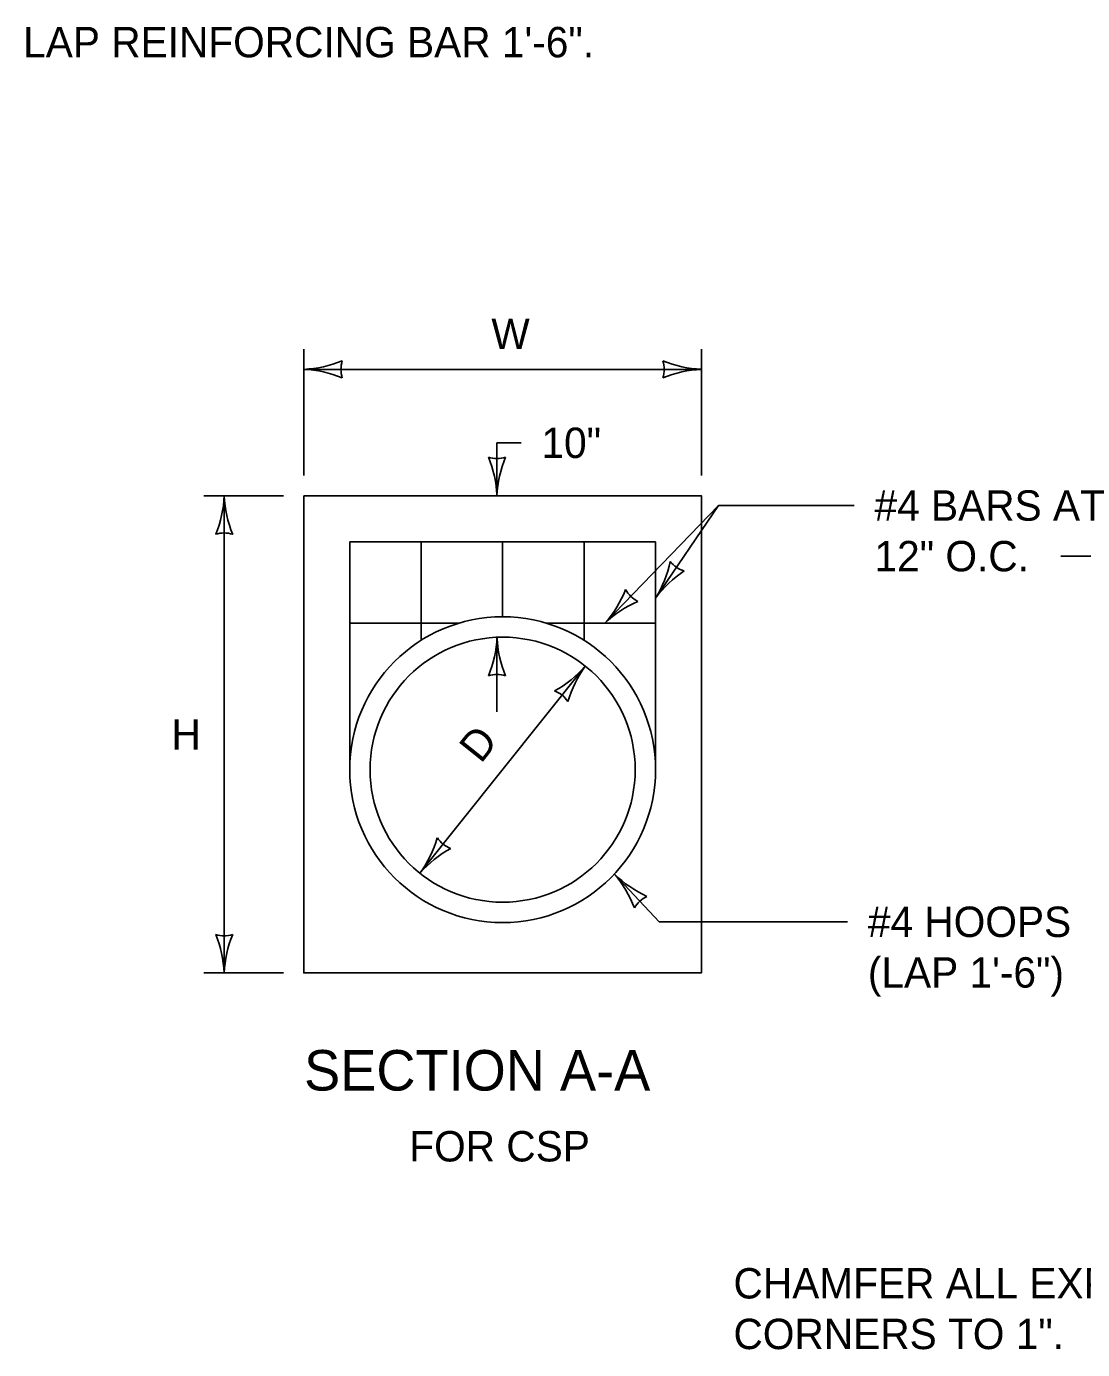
# Model space of a CAD drawing. Extents: x 49991.4 to 50043, y 49987.6 to 50011.4.
# Drawn here: x 50003.119 to 50005.204, y 49993.582 to 49996.195 of the extents above; entities that cross this region are included whole.
import ezdxf

# ---------------------------------------------------------------- set-up
doc = ezdxf.new("R2010")
doc.units = 0
for name, color, linetype in [('Level 1', 7, 'Continuous'), ('Level 2', 7, 'Continuous'), ('Level 3', 7, 'Continuous')]:
    doc.layers.add(name, color=color, linetype=linetype)

msp = doc.modelspace()

# ---------------------------------------------------------------- linework, layer by layer
at = {"layer": 'Level 1'}
for p, q in [((50003.7573, 49995.1771), (50004.3611, 49995.1771)), ((50003.7573, 49994.727), (50003.7573, 49995.1771)), ((50003.8984, 49995.1771), (50003.8984, 49994.9825)), ((50004.0592, 49995.0289), (50004.0592, 49995.1771)), ((50004.22, 49995.1771), (50004.22, 49994.9825)), ((50004.3611, 49995.1771), (50004.3611, 49994.727)), ((50003.7573, 49995.0164), (50003.9732, 49995.0164)), ((50004.1452, 49995.0164), (50004.3611, 49995.0164))]:
    msp.add_line(p, q, dxfattribs=at)
msp.add_lwpolyline([(50003.6666, 49995.2678), (50004.4518, 49995.2678), (50004.4518, 49994.3256), (50003.6666, 49994.3256)], close=True, dxfattribs=at)
for radius in [0.3019, 0.2617]:
    msp.add_circle((50004.0592, 49994.727), radius, dxfattribs=at)
at = {"layer": 'Level 3'}
for p, q in [((50003.6666, 49995.3078), (50003.6666, 49995.5576)), ((50004.4518, 49995.3078), (50004.4518, 49995.5576)), ((50003.6666, 49995.5176), (50004.4518, 49995.5176)), ((50004.0481, 49995.2678), (50004.0481, 49995.3725)), ((50004.0481, 49995.3725), (50004.0959, 49995.3725)), ((50003.6266, 49995.2678), (50003.4695, 49995.2678)), ((50003.5095, 49995.2678), (50003.5095, 49994.3256)), ((50004.4857, 49995.2487), (50004.2613, 49995.0164)), ((50004.4857, 49995.2487), (50004.3611, 49995.0659)), ((50004.7534, 49995.2487), (50004.4857, 49995.2487)), ((50005.1614, 49995.1487), (50005.8063, 49995.1488)), ((50004.0481, 49994.9885), (50004.0481, 49994.841)), ((50003.896, 49994.5224), (50004.2224, 49994.9316)), ((50004.3681, 49994.4266), (50004.2798, 49994.5209)), ((50004.7403, 49994.4266), (50004.3681, 49994.4266)), ((50003.6266, 49994.3256), (50003.4695, 49994.3256))]:
    msp.add_line(p, q, dxfattribs=at)
for centre, radius, start, end in [((50003.6551, 49995.7503), 0.233, 272.8273, 292.0772), ((50003.7948, 49995.5176), 0.0548, 162.1388, 197.8612), ((50004.461, 49995.7398), 0.2223, 247.456, 267.6395), ((50004.3236, 49995.5176), 0.0548, 342.1388, 17.8612), ((50003.6574, 49995.2955), 0.2223, 67.456, 87.6395), ((50004.4633, 49995.2849), 0.233, 92.8273, 112.0772), ((50004.0481, 49995.396), 0.0548, 252.1388, 287.8612), ((50003.8154, 49995.2563), 0.233, 2.8273, 22.0772), ((50004.2702, 49995.2587), 0.2223, 157.456, 177.6395), ((50003.2874, 49995.277), 0.2223, 337.456, 357.6395), ((50003.7422, 49995.2793), 0.233, 182.8273, 202.0772), ((50003.5095, 49995.1396), 0.0548, 72.1388, 107.8612), ((50004.1623, 49995.1875), 0.233, 328.555, 347.8049), ((50004.4333, 49995.1719), 0.0548, 217.8665, 253.5889), ((50004.5395, 49994.9333), 0.2223, 123.1837, 143.3672), ((50004.0859, 49995.1698), 0.233, 318.8188, 338.0686), ((50004.3504, 49995.1086), 0.0548, 208.1303, 243.8526), ((50004.4147, 49994.8555), 0.2223, 113.4475, 133.631), ((50003.826, 49994.9976), 0.2223, 337.456, 357.6395), ((50004.2808, 49995), 0.233, 182.8273, 202.0772), ((50004.0544, 49995.0773), 0.2223, 298.8783, 319.0618), ((50004.4115, 49994.7955), 0.233, 144.2496, 163.4994), ((50004.0481, 49994.8603), 0.0548, 72.1388, 107.8612), ((50004.1424, 49994.8314), 0.0548, 33.5611, 69.2834), ((50003.7069, 49994.6586), 0.233, 324.2496, 343.4994), ((50003.976, 49994.6227), 0.0548, 213.5611, 249.2834), ((50004.064, 49994.3768), 0.2223, 118.8783, 139.0618), ((50004.1114, 49994.3757), 0.2223, 20.5942, 40.7777), ((50004.4417, 49994.6884), 0.233, 225.9655, 245.2153), ((50004.3675, 49994.4273), 0.0548, 115.277, 150.9993), ((50003.5095, 49994.4538), 0.0548, 252.1388, 287.8612), ((50003.2768, 49994.3141), 0.233, 2.8273, 22.0772), ((50003.7316, 49994.3165), 0.2223, 157.456, 177.6395)]:
    msp.add_arc(centre, radius, start, end, dxfattribs=at)

# ---------------------------------------------------------------- texts
at = {"layer": 'Level 2'}
for s, height, p in [('LAP REINFORCING BAR 1\'-6".', 0.06, (50003.1126, 49996.1338)), ('W', 0.06, (50004.037, 49995.5576)), ('10"', 0.06, (50004.1359, 49995.3425)), ('#4 BARS AT ', 0.06, (50004.7934, 49995.2187)), ('12" O.C.', 0.06, (50004.7934, 49995.1187)), ('H', 0.06, (50003.4055, 49994.7667)), ('#4 HOOPS', 0.06, (50004.7803, 49994.3966)), ('(LAP 1\'-6")', 0.06, (50004.7803, 49994.2966)), ('SECTION A-A', 0.08, (50003.6672, 49994.0933)), ('FOR CSP', 0.06, (50003.8749, 49993.9533)), ('CHAMFER ALL EXPOSED', 0.06, (50004.515, 49993.6827)), ('CORNERS TO 1".', 0.06, (50004.515, 49993.5827))]:
    msp.add_text(s, height=height, dxfattribs=at).set_placement(p)
msp.add_text('D', height=0.06, rotation=51.4222, dxfattribs=at).set_placement((50004.0163, 49994.7374))

doc.saveas('drawing.dxf')
